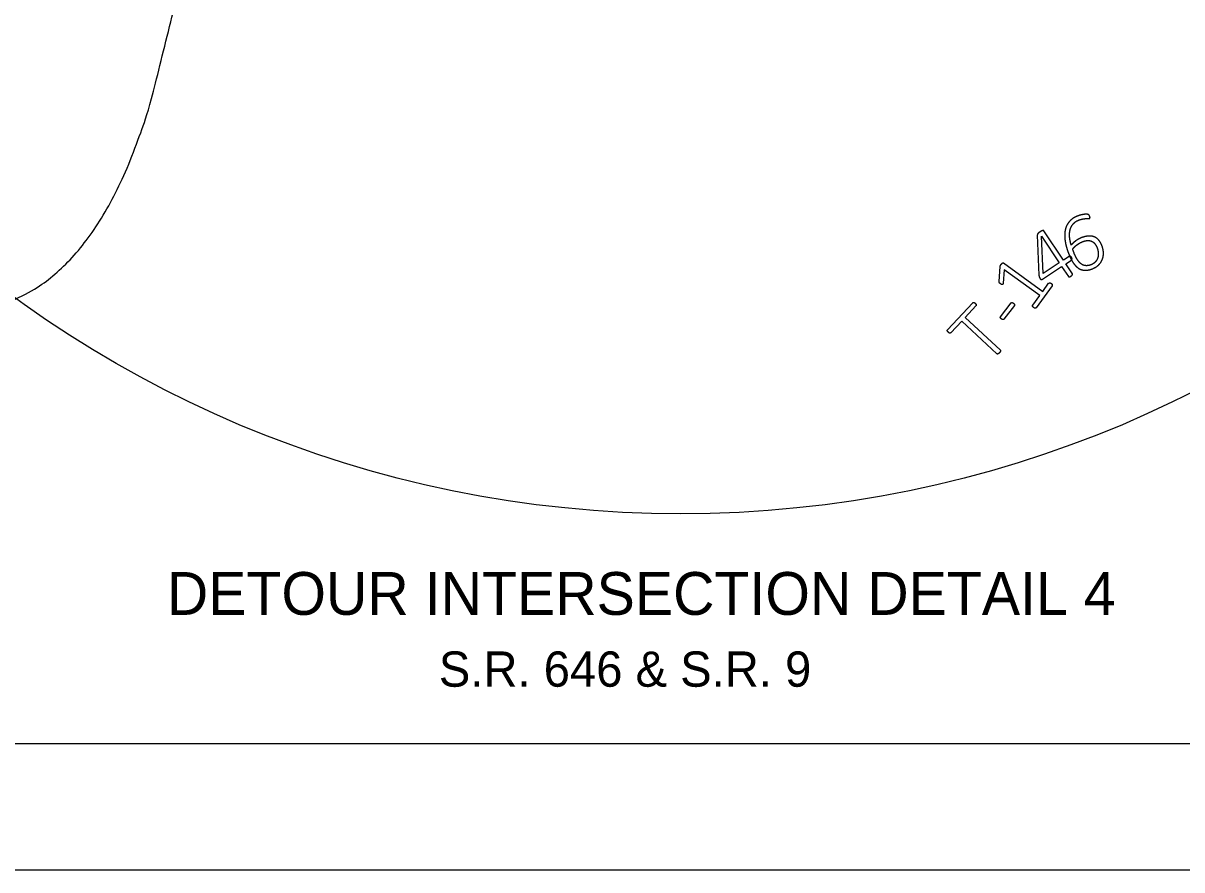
# Model space of a CAD drawing. Extents: x -740 to 1519, y 0 to 440.
# Drawn here: x 442.8 to 534.8, y 0 to 67.2 of the extents above; entities that cross this region are included whole.
import ezdxf

# ---------------------------------------------------------------- set-up
doc = ezdxf.new("R2010")
doc.units = 0
for name, color, linetype in [('GM_X_Section', 7, 'Continuous'), ('GM_X_Township_Text', 7, 'Continuous'), ('SH_Border', 7, 'Continuous'), ('SH_Cut_Line', 7, 'Continuous'), ('SH_Data', 7, 'Continuous')]:
    doc.layers.add(name, color=color, linetype=linetype)

msp = doc.modelspace()

# ---------------------------------------------------------------- linework, layer by layer
at = {"layer": 'GM_X_Township_Text'}
for p, q in [((523.283, 50.366), (523.415, 47.191)), ((528.06, 49.268), (528.06, 49.268)), ((528.445, 49.44), (528.445, 49.44)), ((520.264, 46.675), (520.337, 47.879)), ((526.001, 48.599), (526.001, 48.599)), ((524.458, 46.342), (523.193, 44.604)), ((524.39, 46.529), (524.39, 46.529)), ((516.162, 42.853), (518.157, 45.003)), ((518.361, 44.953), (518.361, 44.953)), ((520.368, 43.894), (521.209, 44.982)), ((521.468, 44.781), (520.627, 43.693)), ((521.397, 44.957), (521.397, 44.957))]:
    msp.add_line(p, q, dxfattribs=at)
for points in [[(525.805, 48.673), (525.356, 48.375), (523.81, 50.708)], [(520.602, 48.153), (523.713, 45.889), (524.186, 46.54)], [(523.697, 46.867), (525.218, 47.875), (525.748, 47.076)], [(526.074, 47.293), (525.544, 48.092), (525.993, 48.39)], [(522.921, 44.802), (523.475, 45.562), (520.66, 47.611), (520.575, 46.562)], [(518.418, 44.761), (517.557, 43.832), (520.357, 41.234)], [(520.085, 40.941), (517.285, 43.539), (516.423, 42.61)]]:
    msp.add_lwpolyline(points, dxfattribs=at)
msp.add_lwpolyline([(523.628, 50.273), (525.03, 48.159), (523.752, 47.312), (523.623, 50.269)], close=True, dxfattribs=at)
for points in [[(526.035, 51.633), (525.817, 51.461), (525.686, 51.246)], [(526.58, 51.916), (526.254, 51.806), (526.035, 51.633)], [(526.146, 51.27), (526.328, 51.476), (526.641, 51.582)], [(526.814, 51.979), (526.695, 51.954), (526.58, 51.916)], [(526.641, 51.582), (526.806, 51.637), (526.934, 51.656)], [(527.039, 52.015), (526.934, 52.004), (526.814, 51.979)], [(526.934, 51.656), (527.062, 51.675), (527.157, 51.676)], [(527.221, 52.021), (527.144, 52.026), (527.039, 52.015)], [(527.157, 51.676), (527.252, 51.677), (527.317, 51.675)], [(527.324, 52.005), (527.297, 52.015), (527.221, 52.021)], [(527.317, 51.675), (527.381, 51.672), (527.416, 51.684)], [(527.367, 51.981), (527.352, 51.995), (527.324, 52.005)], [(527.395, 51.951), (527.382, 51.967), (527.367, 51.981)], [(527.418, 51.911), (527.407, 51.934), (527.395, 51.951)], [(527.416, 51.684), (527.44, 51.692), (527.452, 51.708)], [(527.44, 51.858), (527.429, 51.889), (527.418, 51.911)], [(527.459, 51.795), (527.451, 51.824), (527.44, 51.858)], [(527.452, 51.708), (527.464, 51.724), (527.466, 51.745)], [(527.466, 51.745), (527.467, 51.767), (527.459, 51.795)], [(523.494, 50.617), (523.437, 50.579), (523.396, 50.546)], [(523.61, 50.685), (523.557, 50.658), (523.494, 50.617)], [(523.701, 50.724), (523.662, 50.712), (523.61, 50.685)], [(523.769, 50.732), (523.74, 50.736), (523.701, 50.724)], [(523.81, 50.708), (523.797, 50.727), (523.769, 50.732)], [(525.503, 50.777), (525.452, 50.524), (525.459, 50.255)], [(525.686, 51.246), (525.554, 51.03), (525.503, 50.777)], [(525.848, 50.211), (525.822, 50.524), (525.894, 50.794)], [(525.894, 50.794), (525.965, 51.063), (526.146, 51.27)], [(523.294, 50.423), (523.284, 50.394), (523.283, 50.366)], [(523.33, 50.482), (523.305, 50.452), (523.294, 50.423)], [(523.396, 50.546), (523.355, 50.512), (523.33, 50.482)], [(525.459, 50.255), (525.467, 49.986), (525.527, 49.707)], [(525.527, 49.707), (525.586, 49.428), (525.676, 49.16)], [(525.972, 49.579), (525.874, 49.899), (525.848, 50.211)], [(526.132, 49.743), (526.042, 49.658), (525.972, 49.579)], [(526.337, 49.911), (526.223, 49.829), (526.132, 49.743)], [(526.585, 50.066), (526.451, 49.993), (526.337, 49.911)], [(526.449, 49.604), (526.558, 49.686), (526.682, 49.754)], [(526.878, 50.192), (526.72, 50.139), (526.585, 50.066)], [(526.682, 49.754), (526.806, 49.821), (526.936, 49.865)], [(527.473, 50.292), (527.216, 50.306), (526.878, 50.192)], [(526.936, 49.865), (527.172, 49.945), (527.353, 49.935)], [(527.353, 49.935), (527.534, 49.925), (527.669, 49.842)], [(527.92, 50.168), (527.73, 50.279), (527.473, 50.292)], [(527.669, 49.842), (527.804, 49.76), (527.899, 49.612)], [(528.237, 49.866), (528.109, 50.057), (527.92, 50.168)], [(528.445, 49.44), (528.365, 49.676), (528.237, 49.866)], [(525.676, 49.16), (525.777, 48.862), (525.89, 48.614)], [(526.09, 49.248), (526.156, 49.339), (526.248, 49.431)], [(526.395, 48.535), (526.237, 48.812), (526.09, 49.248)], [(526.248, 49.431), (526.34, 49.522), (526.449, 49.604)], [(527.899, 49.612), (527.994, 49.464), (528.06, 49.268)], [(528.06, 49.268), (528.116, 49.1), (528.123, 48.91)], [(528.123, 48.91), (528.13, 48.72), (528.07, 48.542)], [(528.441, 48.426), (528.539, 48.668), (528.533, 48.933)], [(528.533, 48.933), (528.527, 49.197), (528.445, 49.44)], [(520.337, 47.879), (520.337, 47.891), (520.342, 47.908)], [(520.342, 47.908), (520.346, 47.925), (520.356, 47.946)], [(520.356, 47.946), (520.365, 47.968), (520.379, 47.99)], [(520.379, 47.99), (520.394, 48.012), (520.415, 48.042)], [(520.415, 48.042), (520.448, 48.087), (520.476, 48.115)], [(520.476, 48.115), (520.505, 48.143), (520.526, 48.156)], [(520.526, 48.156), (520.548, 48.168), (520.567, 48.167)], [(520.567, 48.167), (520.586, 48.165), (520.602, 48.153)], [(525.903, 48.687), (525.852, 48.704), (525.805, 48.673)], [(525.89, 48.614), (526.003, 48.367), (526.134, 48.172)], [(526.001, 48.599), (525.954, 48.669), (525.903, 48.687)], [(525.993, 48.39), (526.043, 48.422), (526.042, 48.479)], [(526.042, 48.479), (526.042, 48.536), (526.001, 48.599)], [(526.134, 48.172), (526.265, 47.978), (526.415, 47.843)], [(526.725, 48.113), (526.552, 48.257), (526.395, 48.535)], [(526.415, 47.843), (526.564, 47.708), (526.74, 47.641)], [(527.091, 47.945), (526.898, 47.969), (526.725, 48.113)], [(527.504, 47.996), (527.284, 47.922), (527.091, 47.945)], [(527.871, 48.219), (527.733, 48.074), (527.504, 47.996)], [(527.56, 47.656), (527.917, 47.777), (528.13, 47.98)], [(528.07, 48.542), (528.009, 48.364), (527.871, 48.219)], [(528.13, 47.98), (528.343, 48.183), (528.441, 48.426)], [(523.415, 47.191), (523.417, 47.153), (523.42, 47.121)], [(523.42, 47.121), (523.423, 47.09), (523.432, 47.061)], [(523.432, 47.061), (523.442, 47.032), (523.457, 47.003)], [(523.457, 47.003), (523.473, 46.974), (523.496, 46.938)], [(523.496, 46.938), (523.523, 46.897), (523.548, 46.874)], [(525.748, 47.076), (525.758, 47.059), (525.774, 47.05)], [(525.774, 47.05), (525.79, 47.041), (525.815, 47.046)], [(525.815, 47.046), (525.839, 47.05), (525.874, 47.065)], [(525.874, 47.065), (525.909, 47.081), (525.955, 47.111)], [(525.955, 47.111), (526.004, 47.144), (526.032, 47.17)], [(526.032, 47.17), (526.06, 47.196), (526.073, 47.217)], [(526.073, 47.217), (526.087, 47.238), (526.086, 47.257)], [(526.086, 47.257), (526.085, 47.276), (526.074, 47.293)], [(526.74, 47.641), (526.917, 47.574), (527.12, 47.575)], [(527.12, 47.575), (527.324, 47.577), (527.56, 47.656)], [(520.268, 46.625), (520.264, 46.647), (520.264, 46.675)], [(520.286, 46.582), (520.273, 46.604), (520.268, 46.625)], [(520.322, 46.54), (520.298, 46.561), (520.286, 46.582)], [(520.379, 46.494), (520.345, 46.519), (520.322, 46.54)], [(520.456, 46.446), (520.422, 46.463), (520.379, 46.494)], [(520.515, 46.435), (520.491, 46.429), (520.456, 46.446)], [(520.555, 46.471), (520.54, 46.442), (520.515, 46.435)], [(520.575, 46.562), (520.571, 46.5), (520.555, 46.471)], [(523.548, 46.874), (523.573, 46.852), (523.599, 46.845)], [(523.599, 46.845), (523.625, 46.839), (523.649, 46.845)], [(523.649, 46.845), (523.672, 46.851), (523.697, 46.867)], [(524.186, 46.54), (524.2, 46.558), (524.222, 46.568)], [(524.222, 46.568), (524.244, 46.579), (524.27, 46.578)], [(524.27, 46.578), (524.296, 46.577), (524.327, 46.565)], [(524.327, 46.565), (524.358, 46.552), (524.39, 46.529)], [(524.39, 46.529), (524.428, 46.502), (524.447, 46.475)], [(524.447, 46.475), (524.467, 46.449), (524.473, 46.424)], [(524.475, 46.378), (524.47, 46.358), (524.458, 46.342)], [(524.473, 46.424), (524.479, 46.399), (524.475, 46.378)], [(518.157, 45.003), (518.173, 45.02), (518.195, 45.027)], [(518.195, 45.027), (518.216, 45.033), (518.242, 45.027)], [(518.242, 45.027), (518.268, 45.021), (518.297, 45.003)], [(518.297, 45.003), (518.327, 44.984), (518.361, 44.953)], [(518.361, 44.953), (518.392, 44.924), (518.411, 44.897)], [(518.411, 44.897), (518.431, 44.87), (518.437, 44.846)], [(518.439, 44.8), (518.434, 44.778), (518.418, 44.761)], [(518.437, 44.846), (518.444, 44.822), (518.439, 44.8)], [(521.209, 44.982), (521.221, 44.997), (521.238, 45.006)], [(521.238, 45.006), (521.256, 45.016), (521.279, 45.014)], [(521.279, 45.014), (521.303, 45.012), (521.332, 44.998)], [(521.332, 44.998), (521.36, 44.985), (521.397, 44.957)], [(521.397, 44.957), (521.472, 44.898), (521.483, 44.856)], [(521.483, 44.856), (521.494, 44.815), (521.468, 44.781)], [(522.912, 44.713), (522.903, 44.738), (522.906, 44.761)], [(522.906, 44.761), (522.908, 44.783), (522.921, 44.802)], [(522.943, 44.663), (522.921, 44.689), (522.912, 44.713)], [(522.996, 44.614), (522.964, 44.637), (522.943, 44.663)], [(523.065, 44.576), (523.034, 44.586), (522.996, 44.614)], [(523.121, 44.567), (523.096, 44.565), (523.065, 44.576)], [(523.164, 44.578), (523.147, 44.569), (523.121, 44.567)], [(523.193, 44.604), (523.182, 44.588), (523.164, 44.578)], [(520.353, 43.816), (520.341, 43.86), (520.368, 43.894)], [(520.437, 43.716), (520.364, 43.772), (520.353, 43.816)], [(520.555, 43.66), (520.51, 43.66), (520.437, 43.716)], [(520.627, 43.693), (520.601, 43.66), (520.555, 43.66)], [(516.144, 42.766), (516.136, 42.791), (516.14, 42.812)], [(516.14, 42.812), (516.144, 42.833), (516.162, 42.853)], [(516.173, 42.713), (516.152, 42.741), (516.144, 42.766)], [(516.227, 42.654), (516.193, 42.685), (516.173, 42.713)], [(516.287, 42.607), (516.258, 42.625), (516.227, 42.654)], [(516.339, 42.585), (516.315, 42.59), (516.287, 42.607)], [(516.385, 42.586), (516.364, 42.58), (516.339, 42.585)], [(516.423, 42.61), (516.405, 42.591), (516.385, 42.586)], [(520.118, 40.924), (520.099, 40.928), (520.085, 40.941)], [(520.16, 40.93), (520.137, 40.92), (520.118, 40.924)], [(520.214, 40.964), (520.183, 40.94), (520.16, 40.93)], [(520.284, 41.03), (520.246, 40.989), (520.214, 40.964)], [(520.344, 41.104), (520.322, 41.07), (520.284, 41.03)], [(520.374, 41.161), (520.365, 41.137), (520.344, 41.104)], [(520.357, 41.234), (520.372, 41.221), (520.377, 41.202)], [(520.377, 41.202), (520.382, 41.184), (520.374, 41.161)]]:
    msp.add_open_spline(points, degree=2, dxfattribs=at)
at = {"layer": 'SH_Border'}
msp.add_lwpolyline([(30, 430), (670, 430), (670, 10), (30, 10)], close=True, dxfattribs=at)
at = {"layer": 'SH_Cut_Line'}
msp.add_lwpolyline([(0, 0), (680, 0), (680, 440), (0, 440)], close=True, dxfattribs=at)
at = {"layer": 'SH_Data'}
msp.add_circle((495, 118.25), 90, dxfattribs=at)
msp.add_open_spline([(412.592, 37.021), (434.928, 41.722), (450.388, 49.268), (457.552, 80.583), (470.561, 102.277), (481.873, 117.18), (486.844, 120.545), (491.87, 123.594)], degree=2, dxfattribs=at)

# ---------------------------------------------------------------- texts
at = {"layer": 'GM_X_Section'}
for s, height, p in [('DETOUR INTERSECTION DETAIL 4', 3.4, (454.222, 20.23)), ('S.R. 646 & S.R. 9', 2.79999, (475.803, 14.53))]:
    msp.add_text(s, height=height, dxfattribs=at).set_placement(p)

doc.saveas('drawing.dxf')
